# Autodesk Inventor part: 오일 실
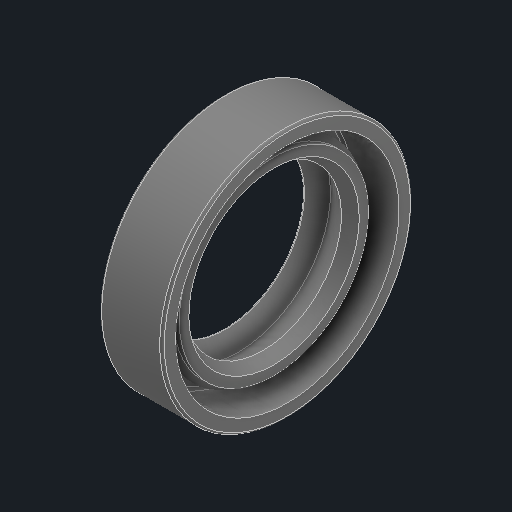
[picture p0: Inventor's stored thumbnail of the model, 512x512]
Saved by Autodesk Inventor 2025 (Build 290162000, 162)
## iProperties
Created: 2025-08
Part Number: 오일 실
Material: 고무
Description: 오일-실
Document SubType Name: Modeling
Designer: infra14
Density: 0.93 g/cm^3
Appearance: 기본값
Author: jhkim
Sending System: Autodesk Inventor 2026
Preprocessor: ST-DEVELOPER v20.1
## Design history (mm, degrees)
feature "Solid1"
node "솔리드1"
